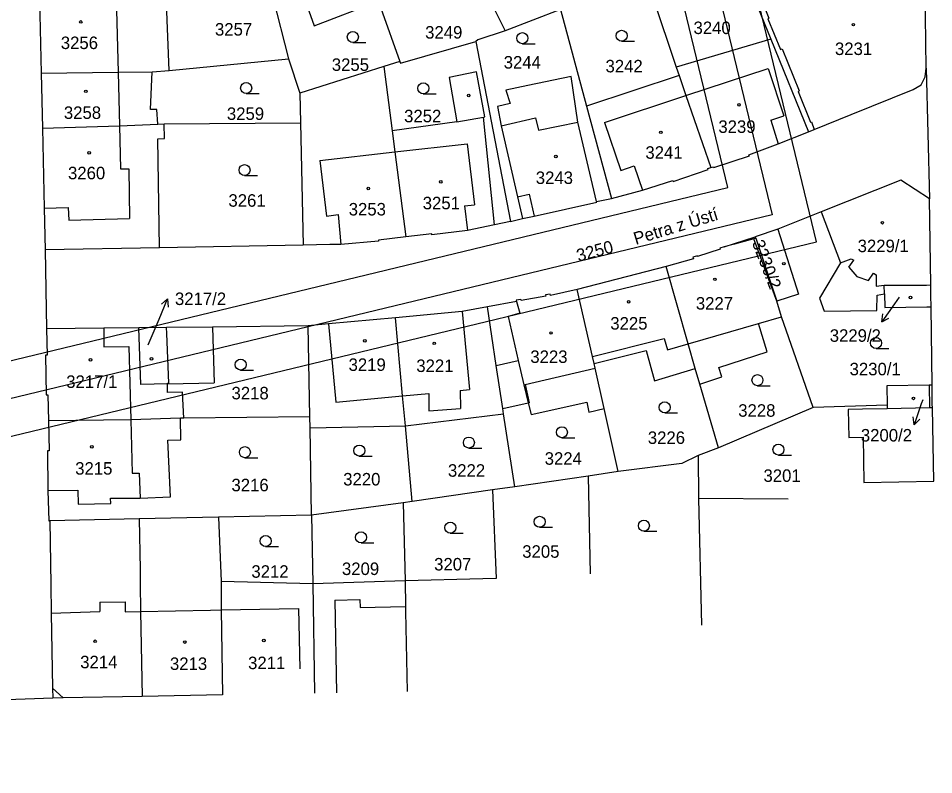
# Model space of a CAD drawing. Extents: x -738085 to -734306, y -1122197 to -1119753.
# Drawn here: x -734573.1 to -734448.6, y -1120345.6 to -1120242.7 of the extents above; entities that cross this region are included whole.
import ezdxf

# ---------------------------------------------------------------- set-up
doc = ezdxf.new("R2010")
doc.units = 0
for name, color, linetype in [('Hranice parcel', 7, 'Continuous'), ('Parcelní čísla', 7, 'Continuous'), ('Pop  PČ popisy', 7, 'Continuous'), ('Vnitřní kresba', 7, 'Continuous'), ('Vrstva 1', 7, 'Continuous'), ('Značky budov', 7, 'Continuous'), ('Značky kultur', 7, 'Continuous')]:
    doc.layers.add(name, color=color, linetype=linetype)

msp = doc.modelspace()

# ---------------------------------------------------------------- linework, layer by layer
at = {"layer": 'Hranice parcel'}
for p, q in [((-734517.37, -1120223.32), (-734506.91, -1120244.39)), ((-734540.41, -1120232.29), (-734536.34, -1120248.22)), ((-734475.99, -1120232.66), (-734470.79, -1120245.51)), ((-734487.77, -1120237.05), (-734483.64, -1120249.33)), ((-734499.39, -1120241.49), (-734506.91, -1120244.39)), ((-734499.39, -1120241.49), (-734495.84, -1120254.63)), ((-734510.86, -1120245.84), (-734506.18, -1120270.34)), ((-734470.79, -1120245.51), (-734483.64, -1120249.33)), ((-734470.79, -1120245.51), (-734465.68, -1120258.12)), ((-734552.58, -1120249.77), (-734536.34, -1120248.22)), ((-734536.34, -1120248.22), (-734534.81, -1120252.87)), ((-734523.37, -1120249.25), (-734534.81, -1120252.87)), ((-734521.21, -1120248.57), (-734523.37, -1120249.25)), ((-734523.37, -1120249.25), (-734522.24, -1120257.98)), ((-734483.64, -1120249.33), (-734483.26, -1120250.45)), ((-734449.65, -1120249.47), (-734449.23, -1120267.25)), ((-734569.95, -1120250.14), (-734569.78, -1120257.61)), ((-734554.89, -1120249.99), (-734552.58, -1120249.77)), ((-734483.26, -1120250.45), (-734495.84, -1120254.63)), ((-734534.81, -1120252.87), (-734534.72, -1120256.89)), ((-734495.84, -1120254.63), (-734492.44, -1120267.19)), ((-734554.12, -1120257.09), (-734553.27, -1120257.06)), ((-734553.27, -1120257.06), (-734534.72, -1120256.89)), ((-734534.72, -1120256.89), (-734534.35, -1120273.53)), ((-734494.47, -1120267.58), (-734492.44, -1120267.19)), ((-734449.01, -1120278.95), (-734449.23, -1120267.25)), ((-734463.95, -1120269.02), (-734469.82, -1120271.38)), ((-734506.18, -1120270.34), (-734508.33, -1120270.79)), ((-734506.18, -1120270.34), (-734504.55, -1120269.91)), ((-734469.95, -1120281.15), (-734473.07, -1120272.7)), ((-734553.9, -1120273.9), (-734569.44, -1120274.19)), ((-734569.44, -1120274.19), (-734569.23, -1120284.91)), ((-734534.35, -1120273.53), (-734553.9, -1120273.9)), ((-734485.01, -1120276.44), (-734497.12, -1120279.58)), ((-734505.35, -1120281.21), (-734509.31, -1120281.93)), ((-734469.33, -1120283.29), (-734469.95, -1120281.15)), ((-734448.86, -1120292.58), (-734449, -1120281.92)), ((-734465.02, -1120295.62), (-734469.33, -1120283.29)), ((-734533.45, -1120296.88), (-734533.67, -1120284.49)), ((-734480.45, -1120292.44), (-734481.06, -1120290.31)), ((-734477.88, -1120301.09), (-734480.45, -1120292.44)), ((-734465.02, -1120295.62), (-734477.88, -1120301.09)), ((-734454.97, -1120295.28), (-734465.02, -1120295.62)), ((-734454.97, -1120295.28), (-734454.96, -1120295.78)), ((-734448.64, -1120305.65), (-734448.82, -1120295.67)), ((-734533.45, -1120296.88), (-734550.59, -1120297.07)), ((-734533.42, -1120298.38), (-734533.45, -1120296.88)), ((-734520.46, -1120298.1), (-734507.1, -1120296.46)), ((-734505.59, -1120306.39), (-734507.1, -1120296.46)), ((-734491.53, -1120304.33), (-734493.43, -1120295.76)), ((-734550.59, -1120297.07), (-734551.01, -1120297.08)), ((-734533.42, -1120298.38), (-734520.46, -1120298.1)), ((-734519.55, -1120308.42), (-734520.46, -1120298.1)), ((-734533.21, -1120310.25), (-734533.42, -1120298.38)), ((-734477.88, -1120301.09), (-734480.64, -1120302.15)), ((-734480.64, -1120302.15), (-734480.62, -1120308.01)), ((-734491.53, -1120304.33), (-734495.6, -1120304.94)), ((-734495.6, -1120304.94), (-734505.59, -1120306.39)), ((-734495.6, -1120304.94), (-734495.32, -1120318.25)), ((-734508.61, -1120306.83), (-734519.55, -1120308.42)), ((-734505.59, -1120306.39), (-734508.61, -1120306.83)), ((-734508.61, -1120306.83), (-734508.13, -1120318.86)), ((-734468.42, -1120308.09), (-734480.62, -1120308.01)), ((-734480.62, -1120308.01), (-734480.22, -1120325.24)), ((-734520.75, -1120308.58), (-734533.21, -1120310.25)), ((-734519.55, -1120308.42), (-734520.75, -1120308.58)), ((-734520.75, -1120308.58), (-734520.49, -1120319.18)), ((-734545.85, -1120310.52), (-734556.66, -1120310.75)), ((-734533.21, -1120310.25), (-734545.85, -1120310.52)), ((-734545.85, -1120310.52), (-734545.5, -1120319.27)), ((-734533.21, -1120310.25), (-734533.05, -1120319.61)), ((-734556.66, -1120310.75), (-734568.79, -1120311.01)), ((-734533.05, -1120319.61), (-734545.5, -1120319.27)), ((-734520.49, -1120319.18), (-734533.05, -1120319.61)), ((-734533.05, -1120319.61), (-734532.79, -1120334.48)), ((-734568.4, -1120335.14), (-734581.22, -1120335.58)), ((-734545.31, -1120334.71), (-734556.23, -1120334.9))]:
    msp.add_line(p, q, dxfattribs=at)
for points in [[(-734537.22, -1120231.46), (-734532.88, -1120243.7), (-734524.13, -1120240.37)], [(-734449.65, -1120249.47), (-734449.76, -1120242.38), (-734449.82, -1120238.13), (-734449.91, -1120232.13)], [(-734552.58, -1120249.77), (-734552.93, -1120240.64), (-734553.34, -1120240.64), (-734553.34, -1120239.63), (-734552.93, -1120239.63), (-734552.93, -1120235.28)], [(-734570.24, -1120237.27), (-734570.18, -1120240.13), (-734569.95, -1120250.14)], [(-734524.13, -1120240.37), (-734523.79, -1120241.29), (-734521.21, -1120248.57)], [(-734506.91, -1120244.39), (-734510.61, -1120245.62), (-734510.86, -1120245.84)], [(-734521.21, -1120248.57), (-734521.13, -1120248.8), (-734510.86, -1120245.84)], [(-734465.68, -1120258.12), (-734464.88, -1120257.8), (-734459.87, -1120255.78), (-734451.43, -1120252.38), (-734450.36, -1120251.73), (-734449.78, -1120250.64), (-734449.65, -1120249.47)], [(-734569.95, -1120250.14), (-734559.52, -1120250.03), (-734554.89, -1120249.99)], [(-734554.12, -1120257.09), (-734554.24, -1120255.08), (-734555.12, -1120255.11), (-734554.89, -1120249.99)], [(-734508.33, -1120270.79), (-734509.85, -1120256.11), (-734509.67, -1120256.08), (-734510.8, -1120249.95), (-734514.49, -1120250.72), (-734513.48, -1120256.78), (-734522.24, -1120257.98)], [(-734494.47, -1120267.58), (-734497.02, -1120256.81), (-734497.93, -1120250.59), (-734503.79, -1120251.84), (-734506.81, -1120252.46), (-734506.2, -1120254.29), (-734507.93, -1120254.69), (-734507.43, -1120257.32), (-734505.22, -1120266.97), (-734504.55, -1120269.91)], [(-734483.26, -1120250.45), (-734482.33, -1120253.19), (-734478.95, -1120263)], [(-734569.78, -1120257.61), (-734559.33, -1120257.29), (-734554.12, -1120257.09)], [(-734553.9, -1120273.9), (-734554.11, -1120259.07), (-734553.19, -1120259.04), (-734553.27, -1120257.06)], [(-734569.78, -1120257.61), (-734569.54, -1120268.51), (-734569.44, -1120274.19)], [(-734522.24, -1120257.98), (-734521.87, -1120260.86), (-734520.4, -1120272.42)], [(-734478.95, -1120263), (-734478.56, -1120262.88), (-734478.52, -1120263), (-734473.7, -1120261.4), (-734473.75, -1120261.27), (-734469.78, -1120259.77), (-734465.68, -1120258.12)], [(-734492.44, -1120267.19), (-734488.23, -1120266.07), (-734484.09, -1120264.74), (-734484.05, -1120264.86), (-734479.3, -1120263.26), (-734479.34, -1120263.13), (-734478.95, -1120263)], [(-734449.23, -1120267.25), (-734453.1, -1120264.68), (-734463.95, -1120269.02)], [(-734504.55, -1120269.91), (-734502.96, -1120269.61), (-734494.44, -1120267.69), (-734494.47, -1120267.58)], [(-734463.95, -1120269.02), (-734461.29, -1120275.96), (-734464.16, -1120280.73), (-734463.55, -1120282.52), (-734456.39, -1120282.43), (-734456.33, -1120280.36), (-734455.33, -1120280.18)], [(-734508.33, -1120270.79), (-734512, -1120271.55), (-734516.84, -1120272.13), (-734516.86, -1120272), (-734520.4, -1120272.42)], [(-734469.82, -1120271.38), (-734472.9, -1120272.39), (-734472.83, -1120272.6), (-734473.07, -1120272.7)], [(-734469.82, -1120271.38), (-734467, -1120280.22), (-734469.95, -1120281.15)], [(-734520.4, -1120272.42), (-734524.13, -1120272.85), (-734524.11, -1120272.99), (-734529.25, -1120273.43), (-734530.71, -1120273.46), (-734534.35, -1120273.53)], [(-734473.07, -1120272.7), (-734475.73, -1120273.4), (-734477.13, -1120273.77), (-734477.71, -1120273.96), (-734477.67, -1120274.08), (-734480.73, -1120275.09), (-734480.77, -1120274.97), (-734481.37, -1120275.17), (-734481.29, -1120275.4), (-734485.01, -1120276.44)], [(-734481.06, -1120290.31), (-734482.01, -1120286.98), (-734485.01, -1120276.44)], [(-734455.33, -1120280.18), (-734455.37, -1120279), (-734449.62, -1120278.98), (-734449.01, -1120278.95)], [(-734449, -1120281.92), (-734449.01, -1120280.37), (-734449.01, -1120278.95)], [(-734497.12, -1120279.58), (-734500.73, -1120280.4), (-734500.77, -1120280.19), (-734501.39, -1120280.3), (-734501.36, -1120280.46), (-734504.72, -1120281.05), (-734504.75, -1120280.92), (-734505.38, -1120281.04), (-734505.35, -1120281.21)], [(-734494.8, -1120289.64), (-734495.02, -1120288.66), (-734497.12, -1120279.58)], [(-734455.33, -1120280.18), (-734455.27, -1120282.03), (-734449.58, -1120281.93), (-734449, -1120281.92)], [(-734509.31, -1120281.93), (-734512.75, -1120282.57), (-734521.81, -1120283.4)], [(-734507.1, -1120296.46), (-734507.21, -1120295.77), (-734508.1, -1120289.92), (-734509.31, -1120281.93)], [(-734505.35, -1120281.21), (-734504.9, -1120282.81), (-734506.49, -1120283.24), (-734505.12, -1120289.23), (-734504.36, -1120292.55), (-734503.75, -1120294.99), (-734503.36, -1120296.56), (-734495.81, -1120294.89), (-734495.54, -1120296.26), (-734493.43, -1120295.76)], [(-734521.81, -1120283.4), (-734530.91, -1120284.24), (-734533.67, -1120284.49)], [(-734520.46, -1120298.1), (-734520.85, -1120294.04), (-734521.81, -1120283.4)], [(-734480.45, -1120292.44), (-734477.43, -1120291.46), (-734477.84, -1120290.19), (-734471.28, -1120288.03), (-734472.44, -1120284.21), (-734469.33, -1120283.29)], [(-734569.23, -1120284.91), (-734569.17, -1120288.52), (-734569.39, -1120288.52), (-734569.3, -1120293.9), (-734569.05, -1120293.89), (-734568.97, -1120297.43)], [(-734556.67, -1120284.76), (-734561.47, -1120284.83), (-734569.23, -1120284.91)], [(-734552.92, -1120284.73), (-734556.6, -1120284.77), (-734556.67, -1120284.76)], [(-734552.79, -1120292.41), (-734556.43, -1120292.49), (-734556.67, -1120284.76)], [(-734533.67, -1120284.49), (-734546.66, -1120284.67), (-734552.92, -1120284.73)], [(-734552.79, -1120292.41), (-734552.79, -1120292.32), (-734552.6, -1120292.31), (-734552.89, -1120285.56), (-734552.92, -1120284.73)], [(-734494.8, -1120289.64), (-734487.74, -1120287.88), (-734486.6, -1120292), (-734481.06, -1120290.31)], [(-734493.43, -1120295.76), (-734494.65, -1120290.27), (-734494.8, -1120289.64)], [(-734550.59, -1120297.07), (-734550.75, -1120293.53), (-734552.81, -1120293.56), (-734552.79, -1120292.41)], [(-734448.86, -1120292.58), (-734449.26, -1120292.59), (-734455.02, -1120292.69), (-734454.97, -1120295.28)], [(-734448.82, -1120295.67), (-734448.83, -1120295.17), (-734448.86, -1120292.58)], [(-734448.82, -1120295.67), (-734449.22, -1120295.68), (-734454.96, -1120295.78)], [(-734454.96, -1120295.78), (-734458.31, -1120295.84), (-734460.26, -1120295.88), (-734460.19, -1120299.68), (-734458.24, -1120299.64), (-734458.14, -1120305.82), (-734448.64, -1120305.65)], [(-734568.97, -1120297.43), (-734568.89, -1120301.5), (-734569.13, -1120301.51), (-734569.05, -1120306.91)], [(-734569.05, -1120306.91), (-734564.98, -1120306.85), (-734564.94, -1120308.75), (-734560.52, -1120308.65), (-734560.54, -1120307.94), (-734556.52, -1120307.93), (-734552.39, -1120307.77), (-734552.74, -1120300.04), (-734550.97, -1120300.02), (-734551.01, -1120297.08)], [(-734551.01, -1120297.08), (-734557.8, -1120297.29), (-734568.97, -1120297.43)], [(-734480.64, -1120302.15), (-734482.89, -1120303.22), (-734491.53, -1120304.33)], [(-734569.05, -1120306.91), (-734568.94, -1120311.01), (-734568.79, -1120311.01)], [(-734568.79, -1120311.01), (-734568.65, -1120319.69), (-734568.59, -1120323.6), (-734568.42, -1120333.79), (-734568.4, -1120335.14)], [(-734556.66, -1120310.75), (-734556.49, -1120317.65), (-734556.49, -1120319.54), (-734556.48, -1120323.35), (-734556.23, -1120334.9)], [(-734545.5, -1120319.27), (-734545.5, -1120323.15), (-734545.31, -1120334.71)], [(-734508.13, -1120318.86), (-734509.92, -1120318.91), (-734520.49, -1120319.18)], [(-734520.49, -1120319.18), (-734520.46, -1120322.7), (-734520.45, -1120323.35), (-734520.2, -1120334.23)], [(-734556.23, -1120334.9), (-734566.98, -1120335.09), (-734568.4, -1120335.14)]]:
    msp.add_lwpolyline(points, dxfattribs=at)
at = {"layer": 'Pop  PČ popisy'}
for p, q in [((-734453.33, -1120280.6), (-734453.99, -1120281.52)), ((-734553.95, -1120283.59), (-734552.78, -1120280.83)), ((-734552.78, -1120280.83), (-734553.63, -1120281.55)), ((-734552.78, -1120280.83), (-734552.71, -1120281.95)), ((-734453.99, -1120281.52), (-734455.71, -1120283.98)), ((-734455.71, -1120283.98), (-734455.55, -1120282.87)), ((-734555.43, -1120287.1), (-734553.95, -1120283.59)), ((-734455.71, -1120283.98), (-734454.73, -1120283.45)), ((-734450.33, -1120295.14), (-734451.31, -1120297.98)), ((-734450.13, -1120294.56), (-734450.33, -1120295.14)), ((-734451.31, -1120297.98), (-734451.45, -1120296.87)), ((-734451.31, -1120297.98), (-734450.51, -1120297.19))]:
    msp.add_line(p, q, dxfattribs=at)
at = {"layer": 'Vnitřní kresba'}
for p, q in [((-734559.78, -1120239.85), (-734559.52, -1120250.03)), ((-734471.5, -1120241.52), (-734471.04, -1120242.69)), ((-734471.17, -1120242.75), (-734471.04, -1120242.69)), ((-734471.17, -1120242.75), (-734469.45, -1120246.94)), ((-734469.45, -1120246.94), (-734469.23, -1120246.85)), ((-734469.23, -1120246.85), (-734466.92, -1120252.57)), ((-734482.33, -1120253.19), (-734471.14, -1120249.51)), ((-734471.14, -1120249.51), (-734468.99, -1120255.96)), ((-734559.52, -1120250.03), (-734559.33, -1120257.29)), ((-734493.4, -1120256.84), (-734482.33, -1120253.19)), ((-734467.08, -1120252.64), (-734466.92, -1120252.57)), ((-734467.08, -1120252.64), (-734465.38, -1120256.82)), ((-734513.48, -1120256.78), (-734509.85, -1120256.11)), ((-734507.43, -1120257.32), (-734502.77, -1120256.22)), ((-734502.77, -1120256.22), (-734502.37, -1120257.9)), ((-734502.37, -1120257.9), (-734497.02, -1120256.81)), ((-734493.4, -1120256.84), (-734491.18, -1120263.38)), ((-734470.77, -1120256.55), (-734468.99, -1120255.96)), ((-734470.77, -1120256.55), (-734469.78, -1120259.77)), ((-734465.38, -1120256.82), (-734465.23, -1120256.76)), ((-734465.23, -1120256.76), (-734464.88, -1120257.8)), ((-734559.33, -1120257.29), (-734559.18, -1120263.17)), ((-734521.87, -1120260.86), (-734512.04, -1120259.74)), ((-734512.04, -1120259.74), (-734511.08, -1120268.05)), ((-734532.1, -1120262.02), (-734521.87, -1120260.86)), ((-734532.1, -1120262.02), (-734531.18, -1120269.59)), ((-734559.18, -1120263.17), (-734558.05, -1120263.15)), ((-734558.05, -1120263.15), (-734557.94, -1120269.92)), ((-734491.18, -1120263.38), (-734489.37, -1120262.77)), ((-734489.37, -1120262.77), (-734488.23, -1120266.07)), ((-734505.22, -1120266.97), (-734503.64, -1120266.61)), ((-734503.64, -1120266.61), (-734502.96, -1120269.61)), ((-734512.4, -1120268.2), (-734511.08, -1120268.05)), ((-734512.4, -1120268.2), (-734512, -1120271.55)), ((-734569.54, -1120268.51), (-734566.28, -1120268.44)), ((-734566.28, -1120268.44), (-734566.19, -1120270.14)), ((-734531.18, -1120269.59), (-734529.59, -1120269.39)), ((-734529.59, -1120269.39), (-734529.25, -1120273.43)), ((-734566.19, -1120270.14), (-734557.94, -1120269.92)), ((-734477.13, -1120273.77), (-734472.9, -1120272.39)), ((-734472.83, -1120272.6), (-734469.95, -1120281.15)), ((-734461.29, -1120275.96), (-734459.88, -1120275.42)), ((-734460.19, -1120276.55), (-734459.49, -1120275.59)), ((-734459.88, -1120275.42), (-734459.49, -1120275.59)), ((-734460.19, -1120276.55), (-734459.09, -1120277.8)), ((-734459.09, -1120277.8), (-734457.5, -1120278.33)), ((-734457.5, -1120278.33), (-734456.83, -1120277.33)), ((-734456.83, -1120277.33), (-734456.45, -1120277.59)), ((-734456.45, -1120277.59), (-734456.44, -1120279.11)), ((-734456.44, -1120279.11), (-734455.37, -1120279)), ((-734512.75, -1120282.57), (-734511.72, -1120293.18)), ((-734530.91, -1120284.24), (-734529.92, -1120294.89)), ((-734482.01, -1120286.98), (-734472.44, -1120284.21)), ((-734561.47, -1120284.83), (-734561.44, -1120287.35)), ((-734546.66, -1120284.67), (-734546.46, -1120292.26)), ((-734495.02, -1120288.66), (-734485.28, -1120286.24)), ((-734485.28, -1120286.24), (-734484.83, -1120287.79)), ((-734561.44, -1120287.35), (-734558.05, -1120287.34)), ((-734558.05, -1120287.34), (-734557.8, -1120297.29)), ((-734484.83, -1120287.79), (-734482.01, -1120286.98)), ((-734508.1, -1120289.92), (-734505.12, -1120289.23)), ((-734504.19, -1120292.51), (-734494.65, -1120290.27)), ((-734552.79, -1120292.41), (-734552.74, -1120292.41)), ((-734552.74, -1120292.41), (-734546.46, -1120292.26)), ((-734513.01, -1120293.3), (-734511.72, -1120293.18)), ((-734504.36, -1120292.55), (-734504.19, -1120292.51)), ((-734504.19, -1120292.51), (-734503.63, -1120294.96)), ((-734449.26, -1120292.59), (-734449.22, -1120295.68)), ((-734529.92, -1120294.89), (-734520.85, -1120294.04)), ((-734520.85, -1120294.04), (-734517.29, -1120293.7)), ((-734517.29, -1120293.7), (-734517.29, -1120296.08)), ((-734513.01, -1120293.3), (-734512.95, -1120295.74)), ((-734507.21, -1120295.77), (-734503.75, -1120294.99)), ((-734503.75, -1120294.99), (-734503.63, -1120294.96)), ((-734517.29, -1120296.08), (-734512.95, -1120295.74)), ((-734557.8, -1120297.29), (-734557.62, -1120304.56)), ((-734557.62, -1120304.56), (-734556.63, -1120304.53)), ((-734556.63, -1120304.53), (-734556.52, -1120307.93)), ((-734530.07, -1120321.8), (-734526.64, -1120321.73)), ((-734530.07, -1120321.8), (-734529.8, -1120334.43)), ((-734526.64, -1120321.73), (-734526.62, -1120322.81)), ((-734562, -1120322.11), (-734558.56, -1120322.06)), ((-734562, -1120322.11), (-734561.98, -1120323.37)), ((-734558.56, -1120322.06), (-734558.54, -1120323.39)), ((-734545.5, -1120323.15), (-734534.98, -1120322.95)), ((-734534.98, -1120322.95), (-734534.81, -1120331.16)), ((-734526.62, -1120322.81), (-734520.46, -1120322.7)), ((-734568.59, -1120323.6), (-734561.98, -1120323.37)), ((-734558.54, -1120323.39), (-734556.48, -1120323.35)), ((-734556.48, -1120323.35), (-734546.96, -1120323.17)), ((-734546.96, -1120323.17), (-734545.5, -1120323.15)), ((-734568.42, -1120333.79), (-734566.98, -1120335.09))]:
    msp.add_line(p, q, dxfattribs=at)
at = {"layer": 'Vrstva 1'}
for points in [[(-734534.27, -1119984.39), (-735554.91, -1120230.88), (-735485.2, -1120519.57), (-734464.55, -1120273.08)], [(-734470.58, -1120269.4), (-735481.51, -1120513.53), (-735548.88, -1120234.56), (-734537.95, -1119990.43)], [(-734541.63, -1119996.45), (-735348.44, -1120191.3), (-735283.42, -1120460.56), (-734476.61, -1120265.71)]]:
    msp.add_lwpolyline(points, close=True, dxfattribs=at)
at = {"layer": 'Značky budov'}
for centre in [(-734564.59, -1120243.18), (-734459.56, -1120243.55), (-734563.89, -1120252.62), (-734511.85, -1120253.18), (-734475.11, -1120254.46), (-734485.73, -1120258.19), (-734563.45, -1120260.98), (-734499.99, -1120261.48), (-734525.5, -1120265.84), (-734515.65, -1120264.92), (-734455.62, -1120270.49), (-734469.01, -1120276.06), (-734478.38, -1120278.19), (-734451.79, -1120280.65), (-734490.11, -1120281.24), (-734500.66, -1120285.48), (-734525.98, -1120286.56), (-734516.53, -1120286.89), (-734563.26, -1120289.13), (-734554.96, -1120288.99), (-734451.4, -1120294.38), (-734563.09, -1120300.97), (-734562.64, -1120327.41), (-734550.44, -1120327.52), (-734539.71, -1120327.3)]:
    msp.add_circle(centre, 0.175, dxfattribs=at)
at = {"layer": 'Značky kultur'}
for p, q in [((-734491.06, -1120245.81), (-734489.31, -1120245.81)), ((-734527.6, -1120245.98), (-734525.85, -1120245.98)), ((-734504.55, -1120246.14), (-734502.8, -1120246.14)), ((-734542.1, -1120252.92), (-734540.35, -1120252.92)), ((-734518.02, -1120252.96), (-734516.27, -1120252.96)), ((-734542.32, -1120264.08), (-734540.57, -1120264.08)), ((-734456.48, -1120287.6), (-734454.73, -1120287.6)), ((-734542.85, -1120290.53), (-734541.1, -1120290.53)), ((-734472.6, -1120292.65), (-734470.85, -1120292.65)), ((-734485.2, -1120296.35), (-734483.45, -1120296.35)), ((-734499.18, -1120299.73), (-734497.43, -1120299.73)), ((-734511.83, -1120301.13), (-734510.08, -1120301.13)), ((-734542.28, -1120302.44), (-734540.53, -1120302.44)), ((-734526.72, -1120302.22), (-734524.97, -1120302.22)), ((-734469.74, -1120302.09), (-734467.99, -1120302.09)), ((-734514.35, -1120312.7), (-734512.6, -1120312.7)), ((-734502.21, -1120311.91), (-734500.46, -1120311.91)), ((-734488.04, -1120312.44), (-734486.29, -1120312.44)), ((-734526.49, -1120314.03), (-734524.74, -1120314.03)), ((-734539.46, -1120314.53), (-734537.71, -1120314.53))]:
    msp.add_line(p, q, dxfattribs=at)
for centre in [(-734527.6, -1120245.23), (-734504.55, -1120245.39), (-734491.06, -1120245.06), (-734542.1, -1120252.17), (-734518.02, -1120252.21), (-734542.32, -1120263.33), (-734456.48, -1120286.85), (-734542.85, -1120289.78), (-734472.6, -1120291.9), (-734485.2, -1120295.6), (-734499.18, -1120298.98), (-734511.83, -1120300.38), (-734469.74, -1120301.34), (-734542.28, -1120301.69), (-734526.72, -1120301.47), (-734502.21, -1120311.16), (-734514.35, -1120311.95), (-734488.04, -1120311.69), (-734539.46, -1120313.78), (-734526.49, -1120313.28)]:
    msp.add_circle(centre, 0.75, dxfattribs=at)

# ---------------------------------------------------------------- texts
at = {"layer": 'Parcelní čísla'}
for s, p in [('3257', (-734546.34, -1120245.04)), ('3240', (-734481.29, -1120244.83)), ('3249', (-734517.77, -1120245.45)), ('3256', (-734567.3, -1120246.87)), ('3231', (-734462.06, -1120247.68)), ('3255', (-734530.46, -1120249.84)), ('3244', (-734507.09, -1120249.52)), ('3242', (-734493.25, -1120250.04)), ('3258', (-734566.88, -1120256.37)), ('3259', (-734544.72, -1120256.51)), ('3252', (-734520.63, -1120256.83)), ('3239', (-734477.91, -1120258.27)), ('3241', (-734487.83, -1120261.79)), ('3260', (-734566.32, -1120264.58)), ('3243', (-734502.73, -1120265.22)), ('3261', (-734544.51, -1120268.31)), ('3251', (-734518.1, -1120268.66)), ('3253', (-734528.16, -1120269.5)), ('3229/1', (-734458.98, -1120274.49)), ('3217/2', (-734551.78, -1120281.68)), ('3227', (-734480.97, -1120282.3)), ('3225', (-734492.6, -1120285.02)), ('3229/2', (-734462.77, -1120286.68)), ('3223', (-734503.47, -1120289.56)), ('3219', (-734528.18, -1120290.64)), ('3221', (-734518.97, -1120290.79)), ('3230/1', (-734460.07, -1120291.24)), ('3217/1', (-734566.56, -1120292.95)), ('3218', (-734544.09, -1120294.51)), ('3228', (-734475.21, -1120296.87)), ('3226', (-734487.5, -1120300.57)), ('3200/2', (-734458.54, -1120300.24)), ('3224', (-734501.52, -1120303.4)), ('3215', (-734565.34, -1120304.75)), ('3222', (-734514.67, -1120305.03)), ('3201', (-734471.78, -1120305.73)), ('3216', (-734544.1, -1120307.01)), ('3220', (-734528.91, -1120306.22)), ('3205', (-734504.57, -1120316.05)), ('3209', (-734529.08, -1120318.4)), ('3207', (-734516.55, -1120317.78)), ('3212', (-734541.39, -1120318.77)), ('3214', (-734564.66, -1120331.08)), ('3213', (-734552.46, -1120331.31)), ('3211', (-734541.84, -1120331.2))]:
    msp.add_text(s, height=1.7, dxfattribs=at).set_placement(p)
for s, rotation, p in [('3250', 15, (-734496.94, -1120275.81)), ('3230/2', 291, (-734473.37, -1120273.2))]:
    msp.add_text(s, height=1.7, rotation=rotation, dxfattribs=at).set_placement(p)
at = {"layer": 'Pop  PČ popisy'}
msp.add_text('Petra z Ústí', height=1.7, rotation=17, dxfattribs=at).set_placement((-734489.14, -1120273.51))

doc.saveas('drawing.dxf')
